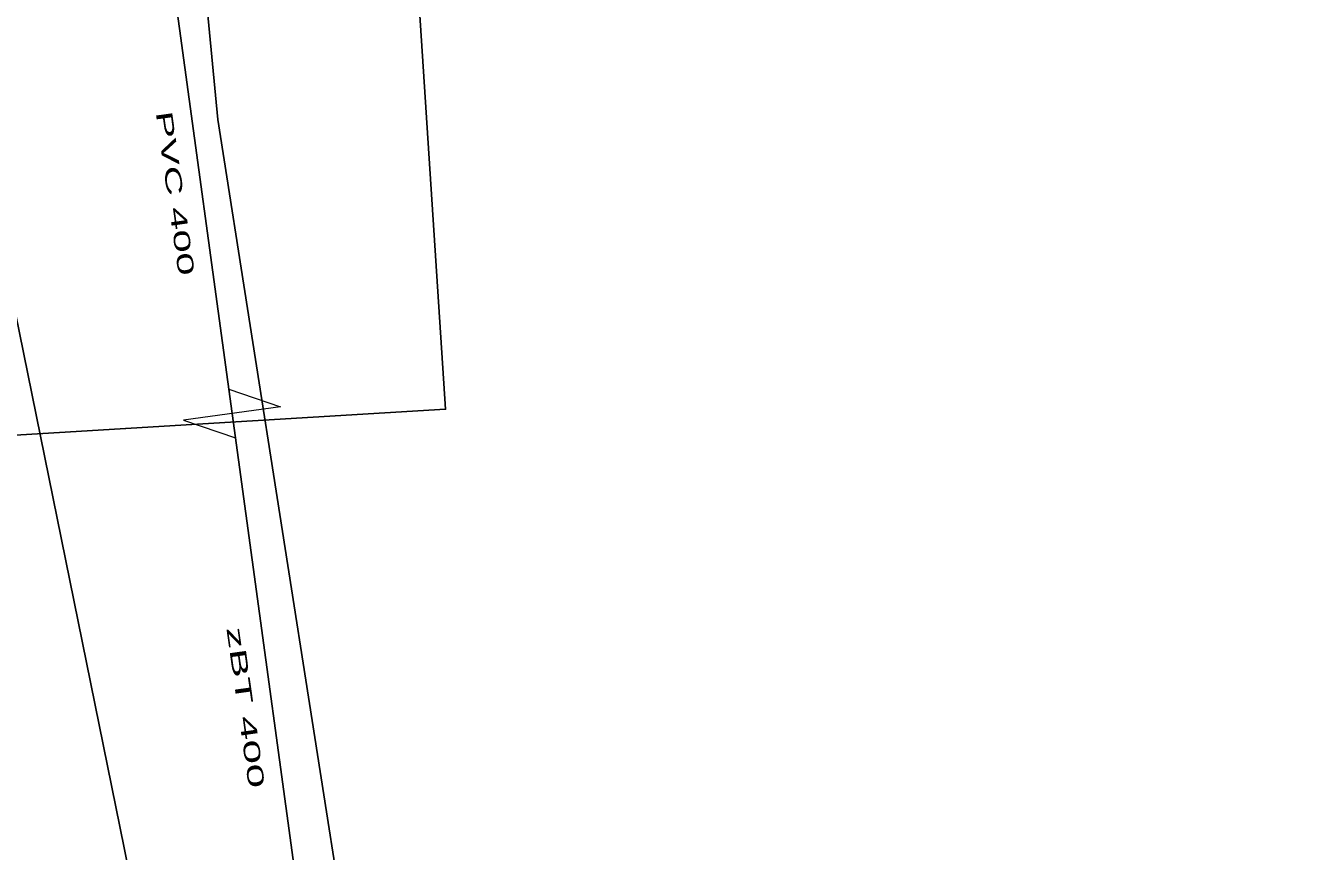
# Model space of a CAD drawing. Extents: x -688432 to -687974, y -973332 to -972704.
# Drawn here: x -688148.9 to -688097.1, y -973001.6 to -972967.8 of the extents above; entities that cross this region are included whole.
import ezdxf
from ezdxf.enums import TextEntityAlignment as Align

# ---------------------------------------------------------------- set-up
doc = ezdxf.new("R2010")
doc.units = 0
doc.header["$LTSCALE"] = 0.27
for name, color, linetype, lineweight in [('1', 7, 'Continuous', 25), ('14', 7, 'Continuous', 25), ('17', 7, 'Continuous', 25), ('31', 7, 'Continuous', 13)]:
    doc.layers.add(name, color=color, linetype=linetype, lineweight=lineweight)

msp = doc.modelspace()

# ---------------------------------------------------------------- linework, layer by layer
at = {"layer": '1'}
msp.add_lwpolyline([(-688157.895, -972985.064), (-688131.748, -972983.489), (-688134.952, -972934.372), (-688122, -972934.52), (-688122.986, -972921.456), (-688135.938, -972921.308), (-688137.958, -972895.554), (-688157.714, -972894.909), (-688157.93, -972929.126), (-688173.215, -972938.189), (-688162.29, -972954.057)], close=True, dxfattribs=at)
at = {"layer": '14'}
msp.add_line((-688140.466, -972983.669), (-688142.909, -972965.839), dxfattribs=at)
msp.add_lwpolyline([(-688132.125, -973025.78), (-688139.776, -973019.199), (-688137.15, -973007.88), (-688140.466, -972983.669)], dxfattribs=at)
at = {"layer": '17'}
for points in [[(-688123.609, -972815.609), (-688135.91, -972839.761), (-688146.524, -972867.704), (-688149.164, -972878.87), (-688150.368, -972974.473), (-688134.778, -973051.136), (-688125.903, -973068.701), (-688203.651, -973132.27), (-688148.612, -973199.748), (-688078.631, -973291.807), (-688049.631, -973331.642)], [(-688050.85, -973016.992), (-688055.169, -973017.307), (-688064.057, -973021.728), (-688087.539, -973032.609), (-688093.627, -973034.653), (-688116.302, -973034.144), (-688128.092, -973024.28), (-688134.442, -973013.736), (-688141.05, -972971.647), (-688145.326, -972926.979)]]:
    msp.add_lwpolyline(points, dxfattribs=at)
at = {"layer": '31'}
msp.add_lwpolyline([(-688140.602, -972982.678), (-688138.485, -972983.397), (-688142.447, -972983.94), (-688140.33, -972984.659)], dxfattribs=at)

# ---------------------------------------------------------------- texts
at = {"layer": '1'}
for s, width, p in [('PVC 400 ', 1.9, (-688143.0872, -972974.9446)), ('PVC 400 ', 1.9, (-688143.0872, -972974.9446)), ('PVC 400 ', 1.9, (-688143.0872, -972974.9446)), ('PVC 400 ', 1.9, (-688143.0872, -972974.9446)), ('PVC 400 ', 1.9, (-688143.0872, -972974.9446)), ('zBT 400 ', 2, (-688140.2087, -972995.9636)), ('zBT 400 ', 2, (-688140.2087, -972995.9636)), ('zBT 400 ', 2, (-688140.2087, -972995.9636)), ('zBT 400 ', 2, (-688140.2087, -972995.9636)), ('zBT 400 ', 2, (-688140.2087, -972995.9636))]:
    msp.add_text(s, height=0.6667, rotation=278, dxfattribs=dict(at, width=width)).set_placement(p, align=Align.CENTER)

doc.saveas('drawing.dxf')
